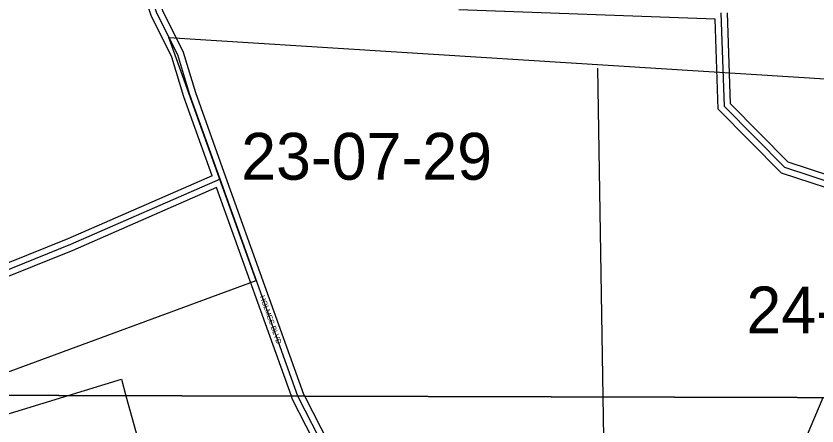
# Model space of a CAD drawing. Extents: x 418523 to 616617, y 1878279 to 2196743.
# Drawn here: x 544272 to 548119, y 2014588 to 2016558 of the extents above; entities that cross this region are included whole.
import ezdxf

# ---------------------------------------------------------------- set-up
doc = ezdxf.new("R2010")
doc.units = 0
for name, color, linetype in [('Level 1', 7, 'Continuous'), ('Level 2', 7, 'Continuous'), ('Level 31', 7, 'Continuous'), ('Level 32', 7, 'Continuous'), ('Level 34', 7, 'Continuous'), ('Level 63', 7, 'Continuous')]:
    doc.layers.add(name, color=color, linetype=linetype)

msp = doc.modelspace()

# ---------------------------------------------------------------- linework, layer by layer
at = {"layer": 'Level 1'}
for p, q in [((545426.357, 2015286.624), (545005.963, 2016454.119)), ((545005.963, 2016454.119), (552297.044, 2015997.651)), ((547091.784, 2014727.856), (547066.583, 2016307.09)), ((543931.171, 2014736.404), (545426.357, 2015286.624)), ((544522.765, 2014734.803), (544778.508, 2014812.6)), ((544778.508, 2014812.6), (544800.238, 2014734.053)), ((544165.694, 2014626.199), (544522.744, 2014734.803)), ((544522.744, 2014734.803), (544522.744, 2014734.803)), ((544522.744, 2014734.803), (544522.745, 2014734.803)), ((544522.745, 2014734.803), (544522.746, 2014734.803)), ((544522.746, 2014734.803), (544522.747, 2014734.803)), ((544522.747, 2014734.803), (544522.748, 2014734.803)), ((544522.748, 2014734.803), (544522.749, 2014734.803)), ((544522.749, 2014734.803), (544522.749, 2014734.803)), ((544522.749, 2014734.803), (544522.75, 2014734.803)), ((544522.75, 2014734.803), (544522.751, 2014734.803)), ((544522.751, 2014734.803), (544522.752, 2014734.803)), ((544522.752, 2014734.803), (544522.753, 2014734.803)), ((544522.753, 2014734.803), (544522.754, 2014734.803)), ((544522.754, 2014734.803), (544522.754, 2014734.803)), ((544522.754, 2014734.803), (544522.755, 2014734.803)), ((544522.755, 2014734.803), (544522.756, 2014734.803)), ((544522.756, 2014734.803), (544522.757, 2014734.803)), ((544522.757, 2014734.803), (544522.758, 2014734.803)), ((544522.758, 2014734.803), (544522.759, 2014734.803)), ((544522.759, 2014734.803), (544522.759, 2014734.803)), ((544522.759, 2014734.803), (544522.76, 2014734.803)), ((544522.76, 2014734.803), (544522.761, 2014734.803)), ((544522.761, 2014734.803), (544522.762, 2014734.803)), ((544522.762, 2014734.803), (544522.763, 2014734.803)), ((544522.763, 2014734.803), (544522.764, 2014734.803)), ((544800.237, 2014734.053), (545212.607, 2013243.442)), ((547094.887, 2014533.398), (547091.783, 2014727.856))]:
    msp.add_line(p, q, dxfattribs=at)
at = {"layer": 'Level 31'}
msp.add_line((545626.455, 2014731.818), (545252.138, 2015773.841), dxfattribs=at)
for points in [[(545252.138, 2015773.841), (545106.623, 2016179.404), (545048.887, 2016371.229), (544949.343, 2016571.546), (544841.94, 2016896.987)], [(548348.15, 2015703.853), (547965.02, 2015829.721), (547673.983, 2016122.603), (547658.517, 2016572.499)], [(545252.138, 2015773.841), (544533.621, 2015459.641), (544141.395, 2015302.284)], [(545760.387, 2014469.302), (545627.73, 2014728.266), (545626.454, 2014731.818)]]:
    msp.add_lwpolyline(points, dxfattribs=at)
at = {"layer": 'Level 32'}
for p, q in [((547629.495, 2016543.521), (546398.612, 2016587.745)), ((545594.547, 2014731.905), (545234.755, 2015733.495)), ((545778.416, 2014499.91), (545659.664, 2014731.729)), ((548068.203, 2014535.874), (548147.82, 2014724.999))]:
    msp.add_line(p, q, dxfattribs=at)
for points in [[(545214.433, 2015790.096), (545078.12, 2016170.008), (545020.89, 2016360.151), (544921.524, 2016560.112), (544814.243, 2016885.184)], [(545280.376, 2015783.973), (545135.125, 2016188.799), (545076.884, 2016382.306), (544977.161, 2016582.98), (544882.624, 2016869.439)], [(548385.212, 2015723.255), (547981.225, 2015855.975), (547703.562, 2016135.399), (547688.484, 2016574.026)], [(548311.091, 2015684.45), (547948.815, 2015803.466), (547644.405, 2016109.807), (547629.496, 2016543.521)], [(545214.433, 2015790.096), (544522.023, 2015487.314), (544130.224, 2015330.128)], [(545659.665, 2014731.729), (545655.313, 2014740.226), (545280.373, 2015783.984)], [(545234.755, 2015733.495), (544545.22, 2015431.969), (544152.565, 2015274.44)], [(545732.013, 2014458.891), (545600.149, 2014716.308), (545594.546, 2014731.905)]]:
    msp.add_lwpolyline(points, dxfattribs=at)
at = {"layer": 'Level 63'}
for points in [[(537381.015, 2014754.121), (576999.64, 2014646.963), (577097.813, 2060104.5), (537528.7, 2060211.986), (537381.015, 2014754.121)], [(537233.895, 1969297.112), (576901.845, 1969190.287), (576999.639, 2014646.963), (537381.014, 2014754.121), (537233.895, 1969297.112)]]:
    msp.add_lwpolyline(points, dxfattribs=at)

# ---------------------------------------------------------------- texts
at = {"layer": 'Level 2'}
for s, p in [('23-07-29', (545353.866, 2015771.603)), ('24-07-29', (547780.135, 2015033.399))]:
    msp.add_text(s, height=225, dxfattribs=at).set_placement(p)
at = {"layer": 'Level 34'}
msp.add_text('HOLMES BLVD', height=25, rotation=289.758419, dxfattribs=at).set_placement((545442.307, 2015210.614))

doc.saveas('drawing.dxf')
